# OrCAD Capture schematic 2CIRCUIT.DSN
size A
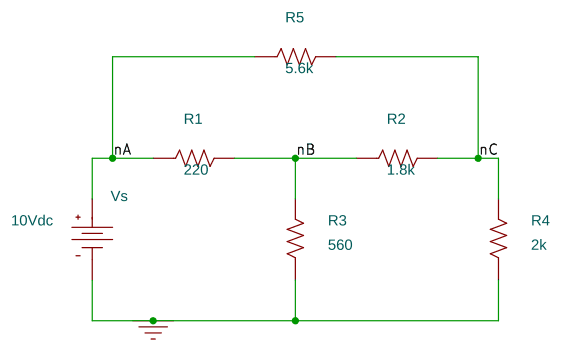
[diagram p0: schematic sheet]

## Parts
R1  220  [AXRC05]
R2  1.8k  [AXRC05]
R3  560  [AXRC05]
R4  2k  [AXRC05]
R5  5.6k  [AXRC05]
Vs  VDC

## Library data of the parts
R1-R5 = R
Vs = VDC: DC: 10Vdc

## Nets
0: R3.1 R4.1 Vs.1(-)
nA: R1.1 R5.1 Vs.0(+)
nB: R1.2 R2.1 R3.2
nC: R2.2 R4.2 R5.2
